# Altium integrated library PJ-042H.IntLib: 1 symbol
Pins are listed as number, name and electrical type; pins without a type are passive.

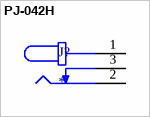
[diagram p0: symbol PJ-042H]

## PJ-042H
designator J?
1.65 mm Center Pin, 2.5 A, Right Angle, Through Hole, Kinked Pins, Dc Power Jack Connector; MF: {'manufacturer': u'CUI'}; MP: PJ-042H
footprint CUI_PJ-042H
pins: 1, 2, 3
